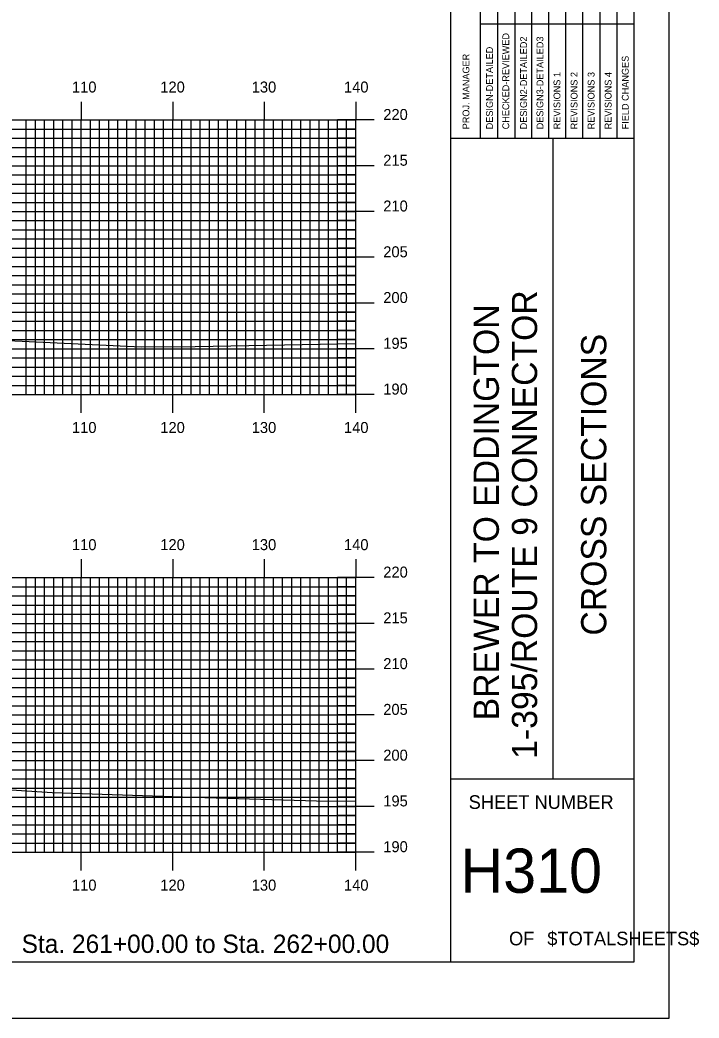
# Model space of a CAD drawing. Extents: x 1806258 to 1806601, y 442591 to 442811.
# Drawn here: x 1806527 to 1806601.2, y 442590.5 to 442699.6 of the extents above; entities that cross this region are included whole.
import ezdxf

# ---------------------------------------------------------------- set-up
doc = ezdxf.new("R2010")
doc.units = 0
for name, color, linetype in [('BORDER', 7, 'Continuous'), ('H_V ANNOTATION', 7, 'Continuous'), ('MAJOR', 7, 'Continuous'), ('MINOR', 7, 'Continuous'), ('PLOT BOUNDARY', 7, 'Continuous'), ('S_Roadway_Centerline', 7, 'Continuous')]:
    doc.layers.add(name, color=color, linetype=linetype)

msp = doc.modelspace()

# ---------------------------------------------------------------- linework, layer by layer
at = {"layer": 'BORDER'}
for p, q in [((1806574.13, 442596.67), (1806574.13, 442806.67)), ((1806574.13, 442686.67), (1806594.13, 442686.67)), ((1806585.31, 442616.67), (1806585.31, 442686.67)), ((1806574.13, 442616.67), (1806594.13, 442616.67))]:
    msp.add_line(p, q, dxfattribs=at)
msp.add_lwpolyline([(1806274.13, 442596.67), (1806594.13, 442596.67), (1806594.13, 442806.67), (1806274.13, 442806.67)], close=True, dxfattribs=at)
for points in [[(1806579.23, 442686.68), (1806579.23, 442721.67)], [(1806581.09, 442721.67), (1806581.09, 442686.68)], [(1806582.95, 442686.68), (1806582.95, 442721.67)], [(1806584.82, 442686.68), (1806584.82, 442721.67)], [(1806586.68, 442686.68), (1806586.68, 442721.67)], [(1806588.54, 442686.68), (1806588.54, 442721.67)], [(1806590.41, 442686.68), (1806590.41, 442721.67)], [(1806592.27, 442686.68), (1806592.27, 442721.67)], [(1806577.36, 442686.68), (1806577.36, 442720.26)], [(1806577.36, 442699.17), (1806594.13, 442699.17)]]:
    msp.add_lwpolyline(points, dxfattribs=at)
at = {"layer": 'MAJOR'}
for p, q in [((1806533.73, 442690.67), (1806533.73, 442688.67)), ((1806543.73, 442690.67), (1806543.73, 442688.67)), ((1806553.73, 442690.67), (1806553.73, 442688.67)), ((1806563.73, 442690.67), (1806563.73, 442688.67)), ((1806283.73, 442688.67), (1806563.73, 442688.67)), ((1806283.73, 442688.67), (1806563.73, 442688.67)), ((1806533.73, 442658.67), (1806533.73, 442688.67)), ((1806543.73, 442658.67), (1806543.73, 442688.67)), ((1806553.73, 442658.67), (1806553.73, 442688.67)), ((1806565.74, 442688.67), (1806561.73, 442688.67)), ((1806563.73, 442658.67), (1806563.73, 442688.67)), ((1806563.73, 442658.67), (1806563.73, 442688.67)), ((1806283.73, 442683.67), (1806563.73, 442683.67)), ((1806565.74, 442683.67), (1806561.73, 442683.67)), ((1806283.73, 442678.67), (1806563.73, 442678.67)), ((1806565.74, 442678.67), (1806561.73, 442678.67)), ((1806283.73, 442673.67), (1806563.73, 442673.67)), ((1806565.74, 442673.67), (1806561.73, 442673.67)), ((1806283.73, 442668.67), (1806563.73, 442668.67)), ((1806565.74, 442668.67), (1806561.73, 442668.67)), ((1806283.73, 442663.67), (1806563.73, 442663.67)), ((1806565.74, 442663.67), (1806561.73, 442663.67)), ((1806283.73, 442658.67), (1806563.73, 442658.67)), ((1806283.73, 442658.67), (1806563.73, 442658.67)), ((1806533.73, 442656.66), (1806533.73, 442658.67)), ((1806543.73, 442656.66), (1806543.73, 442658.67)), ((1806553.73, 442656.66), (1806553.73, 442658.67)), ((1806565.74, 442658.67), (1806561.73, 442658.67)), ((1806563.73, 442656.66), (1806563.73, 442658.67)), ((1806533.73, 442640.67), (1806533.73, 442638.67)), ((1806543.73, 442640.67), (1806543.73, 442638.67)), ((1806553.73, 442640.67), (1806553.73, 442638.67)), ((1806563.73, 442640.67), (1806563.73, 442638.67)), ((1806283.73, 442638.67), (1806563.73, 442638.67)), ((1806283.73, 442638.67), (1806563.73, 442638.67)), ((1806533.73, 442608.67), (1806533.73, 442638.67)), ((1806543.73, 442608.67), (1806543.73, 442638.67)), ((1806553.73, 442608.67), (1806553.73, 442638.67)), ((1806565.74, 442638.67), (1806561.73, 442638.67)), ((1806563.73, 442608.67), (1806563.73, 442638.67)), ((1806563.73, 442608.67), (1806563.73, 442638.67)), ((1806283.73, 442633.67), (1806563.73, 442633.67)), ((1806565.74, 442633.67), (1806561.73, 442633.67)), ((1806283.73, 442628.67), (1806563.73, 442628.67)), ((1806565.74, 442628.67), (1806561.73, 442628.67)), ((1806283.73, 442623.67), (1806563.73, 442623.67)), ((1806565.74, 442623.67), (1806561.73, 442623.67)), ((1806283.73, 442618.67), (1806563.73, 442618.67)), ((1806565.74, 442618.67), (1806561.73, 442618.67)), ((1806283.73, 442613.67), (1806563.73, 442613.67)), ((1806565.74, 442613.67), (1806561.73, 442613.67)), ((1806283.73, 442608.67), (1806563.73, 442608.67)), ((1806283.73, 442608.67), (1806563.73, 442608.67)), ((1806533.73, 442606.66), (1806533.73, 442608.67)), ((1806543.73, 442606.66), (1806543.73, 442608.67)), ((1806553.73, 442606.66), (1806553.73, 442608.67)), ((1806565.74, 442608.67), (1806561.73, 442608.67)), ((1806563.73, 442606.66), (1806563.73, 442608.67))]:
    msp.add_line(p, q, dxfattribs=at)
at = {"layer": 'MINOR'}
for p, q in [((1806527.73, 442658.67), (1806527.73, 442688.67)), ((1806528.73, 442658.67), (1806528.73, 442688.67)), ((1806529.73, 442658.67), (1806529.73, 442688.67)), ((1806530.73, 442658.67), (1806530.73, 442688.67)), ((1806531.73, 442658.67), (1806531.73, 442688.67)), ((1806532.73, 442658.67), (1806532.73, 442688.67)), ((1806534.73, 442658.67), (1806534.73, 442688.67)), ((1806535.73, 442658.67), (1806535.73, 442688.67)), ((1806536.73, 442658.67), (1806536.73, 442688.67)), ((1806537.73, 442658.67), (1806537.73, 442688.67)), ((1806538.73, 442658.67), (1806538.73, 442688.67)), ((1806539.73, 442658.67), (1806539.73, 442688.67)), ((1806540.73, 442658.67), (1806540.73, 442688.67)), ((1806541.73, 442658.67), (1806541.73, 442688.67)), ((1806542.73, 442658.67), (1806542.73, 442688.67)), ((1806544.73, 442658.67), (1806544.73, 442688.67)), ((1806545.73, 442658.67), (1806545.73, 442688.67)), ((1806546.73, 442658.67), (1806546.73, 442688.67)), ((1806547.73, 442658.67), (1806547.73, 442688.67)), ((1806548.73, 442658.67), (1806548.73, 442688.67)), ((1806549.73, 442658.67), (1806549.73, 442688.67)), ((1806550.73, 442658.67), (1806550.73, 442688.67)), ((1806551.73, 442658.67), (1806551.73, 442688.67)), ((1806552.73, 442658.67), (1806552.73, 442688.67)), ((1806554.73, 442658.67), (1806554.73, 442688.67)), ((1806555.73, 442658.67), (1806555.73, 442688.67)), ((1806556.73, 442658.67), (1806556.73, 442688.67)), ((1806557.73, 442658.67), (1806557.73, 442688.67)), ((1806558.73, 442658.67), (1806558.73, 442688.67)), ((1806559.73, 442658.67), (1806559.73, 442688.67)), ((1806560.73, 442658.67), (1806560.73, 442688.67)), ((1806561.73, 442658.67), (1806561.73, 442688.67)), ((1806562.73, 442658.67), (1806562.73, 442688.67)), ((1806283.73, 442687.67), (1806563.73, 442687.67)), ((1806563.73, 442687.67), (1806561.73, 442687.67)), ((1806283.73, 442686.67), (1806563.73, 442686.67)), ((1806563.73, 442686.67), (1806561.73, 442686.67)), ((1806283.73, 442685.67), (1806563.73, 442685.67)), ((1806563.73, 442685.67), (1806561.73, 442685.67)), ((1806283.73, 442684.67), (1806563.73, 442684.67)), ((1806563.73, 442684.67), (1806561.73, 442684.67)), ((1806283.73, 442682.67), (1806563.73, 442682.67)), ((1806563.73, 442682.67), (1806561.73, 442682.67)), ((1806283.73, 442681.67), (1806563.73, 442681.67)), ((1806563.73, 442681.67), (1806561.73, 442681.67)), ((1806283.73, 442680.67), (1806563.73, 442680.67)), ((1806283.73, 442679.67), (1806563.73, 442679.67)), ((1806563.73, 442680.67), (1806561.73, 442680.67)), ((1806563.73, 442679.67), (1806561.73, 442679.67)), ((1806283.73, 442677.67), (1806563.73, 442677.67)), ((1806563.73, 442677.67), (1806561.73, 442677.67)), ((1806283.73, 442676.67), (1806563.73, 442676.67)), ((1806563.73, 442676.67), (1806561.73, 442676.67)), ((1806283.73, 442675.67), (1806563.73, 442675.67)), ((1806563.73, 442675.67), (1806561.73, 442675.67)), ((1806283.73, 442674.67), (1806563.73, 442674.67)), ((1806563.73, 442674.67), (1806561.73, 442674.67)), ((1806283.73, 442672.67), (1806563.73, 442672.67)), ((1806563.73, 442672.67), (1806561.73, 442672.67)), ((1806283.73, 442671.67), (1806563.73, 442671.67)), ((1806563.73, 442671.67), (1806561.73, 442671.67)), ((1806283.73, 442670.67), (1806563.73, 442670.67)), ((1806563.73, 442670.67), (1806561.73, 442670.67)), ((1806283.73, 442669.67), (1806563.73, 442669.67)), ((1806563.73, 442669.67), (1806561.73, 442669.67)), ((1806283.73, 442667.67), (1806563.73, 442667.67)), ((1806563.73, 442667.67), (1806561.73, 442667.67)), ((1806283.73, 442666.67), (1806563.73, 442666.67)), ((1806563.73, 442666.67), (1806561.73, 442666.67)), ((1806283.73, 442665.67), (1806563.73, 442665.67)), ((1806563.73, 442665.67), (1806561.73, 442665.67)), ((1806283.73, 442664.67), (1806563.73, 442664.67)), ((1806563.73, 442664.67), (1806561.73, 442664.67)), ((1806283.73, 442662.67), (1806563.73, 442662.67)), ((1806563.73, 442662.67), (1806561.73, 442662.67)), ((1806283.73, 442661.67), (1806563.73, 442661.67)), ((1806563.73, 442661.67), (1806561.73, 442661.67)), ((1806283.73, 442660.67), (1806563.73, 442660.67)), ((1806563.73, 442660.67), (1806561.73, 442660.67)), ((1806283.73, 442659.67), (1806563.73, 442659.67)), ((1806563.73, 442659.67), (1806561.73, 442659.67)), ((1806527.73, 442608.67), (1806527.73, 442638.67)), ((1806528.73, 442608.67), (1806528.73, 442638.67)), ((1806529.73, 442608.67), (1806529.73, 442638.67)), ((1806530.73, 442608.67), (1806530.73, 442638.67)), ((1806531.73, 442608.67), (1806531.73, 442638.67)), ((1806532.73, 442608.67), (1806532.73, 442638.67)), ((1806534.73, 442608.67), (1806534.73, 442638.67)), ((1806535.73, 442608.67), (1806535.73, 442638.67)), ((1806536.73, 442608.67), (1806536.73, 442638.67)), ((1806537.73, 442608.67), (1806537.73, 442638.67)), ((1806538.73, 442608.67), (1806538.73, 442638.67)), ((1806539.73, 442608.67), (1806539.73, 442638.67)), ((1806540.73, 442608.67), (1806540.73, 442638.67)), ((1806541.73, 442608.67), (1806541.73, 442638.67)), ((1806542.73, 442608.67), (1806542.73, 442638.67)), ((1806544.73, 442608.67), (1806544.73, 442638.67)), ((1806545.73, 442608.67), (1806545.73, 442638.67)), ((1806546.73, 442608.67), (1806546.73, 442638.67)), ((1806547.73, 442608.67), (1806547.73, 442638.67)), ((1806548.73, 442608.67), (1806548.73, 442638.67)), ((1806549.73, 442608.67), (1806549.73, 442638.67)), ((1806550.73, 442608.67), (1806550.73, 442638.67)), ((1806551.73, 442608.67), (1806551.73, 442638.67)), ((1806552.73, 442608.67), (1806552.73, 442638.67)), ((1806554.73, 442608.67), (1806554.73, 442638.67)), ((1806555.73, 442608.67), (1806555.73, 442638.67)), ((1806556.73, 442608.67), (1806556.73, 442638.67)), ((1806557.73, 442608.67), (1806557.73, 442638.67)), ((1806558.73, 442608.67), (1806558.73, 442638.67)), ((1806559.73, 442608.67), (1806559.73, 442638.67)), ((1806560.73, 442608.67), (1806560.73, 442638.67)), ((1806561.73, 442608.67), (1806561.73, 442638.67)), ((1806562.73, 442608.67), (1806562.73, 442638.67)), ((1806283.73, 442637.67), (1806563.73, 442637.67)), ((1806563.73, 442637.67), (1806561.73, 442637.67)), ((1806283.73, 442636.67), (1806563.73, 442636.67)), ((1806563.73, 442636.67), (1806561.73, 442636.67)), ((1806283.73, 442635.67), (1806563.73, 442635.67)), ((1806563.73, 442635.67), (1806561.73, 442635.67)), ((1806283.73, 442634.67), (1806563.73, 442634.67)), ((1806563.73, 442634.67), (1806561.73, 442634.67)), ((1806283.73, 442632.67), (1806563.73, 442632.67)), ((1806563.73, 442632.67), (1806561.73, 442632.67)), ((1806283.73, 442631.67), (1806563.73, 442631.67)), ((1806283.73, 442630.67), (1806563.73, 442630.67)), ((1806563.73, 442631.67), (1806561.73, 442631.67)), ((1806563.73, 442630.67), (1806561.73, 442630.67)), ((1806283.73, 442629.67), (1806563.73, 442629.67)), ((1806563.73, 442629.67), (1806561.73, 442629.67)), ((1806283.73, 442627.67), (1806563.73, 442627.67)), ((1806563.73, 442627.67), (1806561.73, 442627.67)), ((1806283.73, 442626.67), (1806563.73, 442626.67)), ((1806563.73, 442626.67), (1806561.73, 442626.67)), ((1806283.73, 442625.67), (1806563.73, 442625.67)), ((1806563.73, 442625.67), (1806561.73, 442625.67)), ((1806283.73, 442624.67), (1806563.73, 442624.67)), ((1806563.73, 442624.67), (1806561.73, 442624.67)), ((1806283.73, 442622.67), (1806563.73, 442622.67)), ((1806563.73, 442622.67), (1806561.73, 442622.67)), ((1806283.73, 442621.67), (1806563.73, 442621.67)), ((1806563.73, 442621.67), (1806561.73, 442621.67)), ((1806283.73, 442620.67), (1806563.73, 442620.67)), ((1806563.73, 442620.67), (1806561.73, 442620.67)), ((1806283.73, 442619.67), (1806563.73, 442619.67)), ((1806563.73, 442619.67), (1806561.73, 442619.67)), ((1806283.73, 442617.67), (1806563.73, 442617.67)), ((1806563.73, 442617.67), (1806561.73, 442617.67)), ((1806283.73, 442616.67), (1806563.73, 442616.67)), ((1806563.73, 442616.67), (1806561.73, 442616.67)), ((1806283.73, 442615.67), (1806563.73, 442615.67)), ((1806563.73, 442615.67), (1806561.73, 442615.67)), ((1806283.73, 442614.67), (1806563.73, 442614.67)), ((1806563.73, 442614.67), (1806561.73, 442614.67)), ((1806283.73, 442612.67), (1806563.73, 442612.67)), ((1806563.73, 442612.67), (1806561.73, 442612.67)), ((1806283.73, 442611.67), (1806563.73, 442611.67)), ((1806563.73, 442611.67), (1806561.73, 442611.67)), ((1806283.73, 442610.67), (1806563.73, 442610.67)), ((1806563.73, 442610.67), (1806561.73, 442610.67)), ((1806283.73, 442609.67), (1806563.73, 442609.67)), ((1806563.73, 442609.67), (1806561.73, 442609.67))]:
    msp.add_line(p, q, dxfattribs=at)
at = {"layer": 'PLOT BOUNDARY'}
msp.add_lwpolyline([(1806257.95, 442590.55), (1806597.95, 442590.55), (1806597.95, 442810.55), (1806257.95, 442810.55)], close=True, dxfattribs=at)
at = {"layer": 'S_Roadway_Centerline'}
for points in [[(1806452.93, 442666.31), (1806456.31, 442666.14), (1806474.47, 442664.87), (1806476.7, 442664.8), (1806488.29, 442664.82), (1806498.37, 442664.63), (1806499.2, 442664.61), (1806500.24, 442664.64), (1806518.57, 442664.92), (1806527.28, 442664.52), (1806540.28, 442663.88), (1806546.17, 442663.92), (1806563.73, 442664.26)], [(1806448.11, 442617.46), (1806463.03, 442616.97), (1806476.28, 442616.54), (1806482.67, 442616.34), (1806491.6, 442615.97), (1806497.72, 442616), (1806506.23, 442616.21), (1806517.73, 442616.01), (1806530.55, 442615.18), (1806544.79, 442614.7), (1806560.67, 442614.25), (1806563.73, 442614.28)]]:
    msp.add_lwpolyline(points, dxfattribs=at)

# ---------------------------------------------------------------- texts
at = {"layer": 'BORDER'}
for s, height, p in [('CHECKED-REVIEWED', 0.7455, (1806580.49, 442687.65)), ('DESIGN2-DETAILED2', 0.7455, (1806582.43, 442687.65)), ('DESIGN3-DETAILED3', 0.7455, (1806584.22, 442687.65)), ('DESIGN-DETAILED', 0.7455, (1806578.71, 442687.65)), ('PROJ. MANAGER', 0.7455, (1806576.14, 442687.65)), ('FIELD CHANGES', 0.7455, (1806593.54, 442687.65)), ('REVISIONS 1', 0.7455, (1806586.08, 442687.65)), ('REVISIONS 2', 0.7455, (1806587.95, 442687.65)), ('REVISIONS 3', 0.7455, (1806589.81, 442687.65)), ('REVISIONS 4', 0.7455, (1806591.67, 442687.65)), ('1-395/ROUTE 9 CONNECTOR', 2.7557, (1806583.54, 442618.87)), ('BREWER TO EDDINGTON', 2.7557, (1806579.36, 442623.07)), ('CROSS SECTIONS', 2.7557, (1806591.1, 442632.34))]:
    msp.add_text(s, height=height, rotation=90, dxfattribs=at).set_placement(p)
for s, height, p in [('SHEET NUMBER', 1.4905, (1806576.06, 442613.4)), ('H310', 4.839, (1806575.16, 442604.23)), ('$TOTALSHEETS$', 1.4905, (1806584.65, 442598.49)), ('OF', 1.491, (1806580.47, 442598.49))]:
    msp.add_text(s, height=height, dxfattribs=at).set_placement(p)
at = {"layer": 'H_V ANNOTATION'}
for s, height, p in [('110', 1.2, (1806532.72, 442691.67)), ('120', 1.2, (1806542.37, 442691.67)), ('130', 1.2, (1806552.36, 442691.67)), ('140', 1.2, (1806562.44, 442691.67)), ('220', 1.2, (1806566.73, 442688.67)), ('215', 1.2, (1806566.73, 442683.67)), ('210', 1.2, (1806566.73, 442678.67)), ('205', 1.2, (1806566.73, 442673.67)), ('200', 1.2, (1806566.73, 442668.67)), ('195', 1.2, (1806566.73, 442663.67)), ('190', 1.2, (1806566.73, 442658.67)), ('110', 1.2, (1806532.72, 442654.47)), ('120', 1.2, (1806542.37, 442654.47)), ('130', 1.2, (1806552.36, 442654.47)), ('140', 1.2, (1806562.44, 442654.47)), ('110', 1.2, (1806532.72, 442641.67)), ('120', 1.2, (1806542.37, 442641.67)), ('130', 1.2, (1806552.36, 442641.67)), ('140', 1.2, (1806562.44, 442641.67)), ('220', 1.2, (1806566.73, 442638.67)), ('215', 1.2, (1806566.73, 442633.67)), ('210', 1.2, (1806566.73, 442628.67)), ('205', 1.2, (1806566.73, 442623.67)), ('200', 1.2, (1806566.73, 442618.67)), ('195', 1.2, (1806566.73, 442613.67)), ('190', 1.2, (1806566.73, 442608.67)), ('110', 1.2, (1806532.72, 442604.47)), ('120', 1.2, (1806542.37, 442604.47)), ('130', 1.2, (1806552.36, 442604.47)), ('140', 1.2, (1806562.44, 442604.47)), ('Sta. 261+00.00 to Sta. 262+00.00', 2.0004, (1806527.22, 442597.66))]:
    msp.add_text(s, height=height, dxfattribs=at).set_placement(p)

doc.saveas('drawing.dxf')
